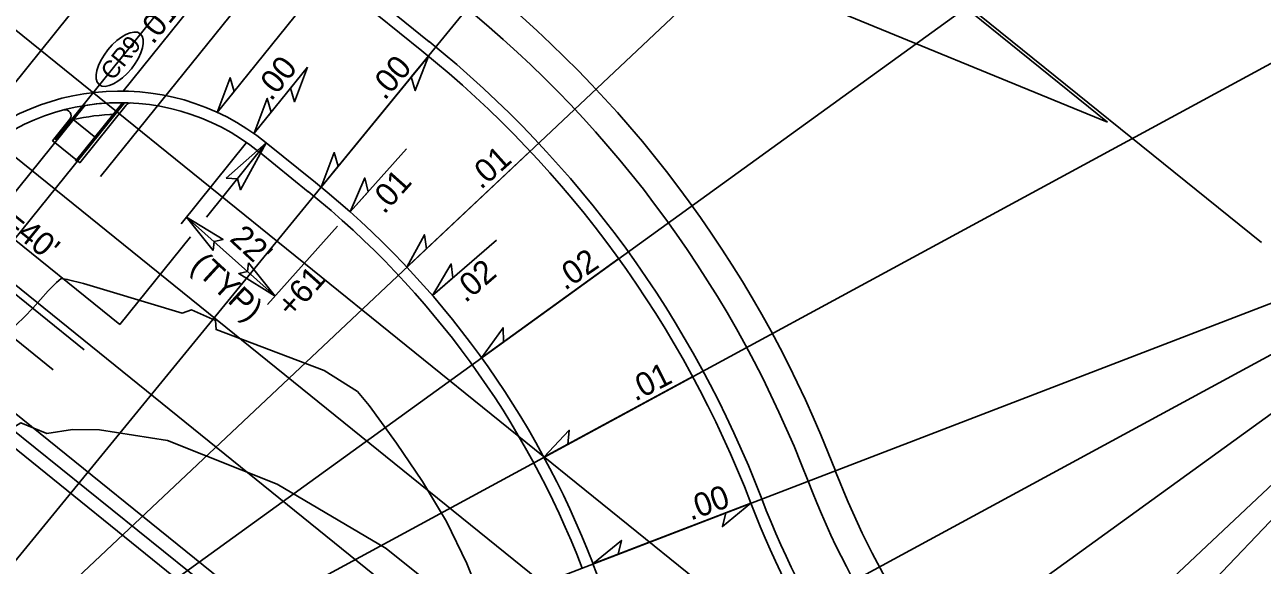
# Model space of a CAD drawing. Extents: x 1486489 to 1490134, y 497089 to 500876.
# Drawn here: x 1488844.3 to 1489056.4, y 499139.1 to 499231.7 of the extents above; entities that cross this region are included whole.
import ezdxf

# ---------------------------------------------------------------- set-up
doc = ezdxf.new("R2010")
doc.units = 0
for name, color, linetype in [('DEV PRELIMINARY STAMP CELL', 7, 'Continuous'), ('Gray Area Fill Shapes', 7, 'Continuous'), ('Old_Level_9', 7, 'Continuous'), ('Pattern 5', 7, 'Continuous'), ('Prop Horizontal Alignment Station Label', 7, 'Continuous'), ('Prop North Arrow NAD83 for Plan Sheets CELL', 7, 'Continuous'), ('Prop Rem of Exist Asph Pvmt', 7, 'Continuous'), ('Prop Text', 7, 'Continuous'), ('Prop WCC CELL', 7, 'Continuous'), ('Scratch_Level_0', 7, 'Continuous'), ('Scratch_Level_5', 7, 'Continuous'), ('Sheet Block Revision CELL', 7, 'Continuous'), ('Sheet Block Title CELL', 7, 'Continuous'), ('Sheet Border Standard 30in CELL', 7, 'Continuous'), ('Sheet Data Field CELL', 7, 'Continuous'), ('Sheet Plan CELL', 7, 'Continuous'), ('Sheet Sticker Exception Certification CELL', 7, 'Continuous')]:
    doc.layers.add(name, color=color, linetype=linetype)

msp = doc.modelspace()

# ---------------------------------------------------------------- linework, layer by layer
at = {"layer": 'DEV PRELIMINARY STAMP CELL'}
for points in [[(1488892.75, 499224.41), (1488890.54, 499218.48), (1488889.84, 499220.81)], [(1488883.65, 499213.12), (1488885.86, 499219.05), (1488886.55, 499216.72)], [(1488900.08, 499199.62), (1488902.59, 499205.43), (1488903.16, 499203.07)], [(1488914.19, 499185.29), (1488917.42, 499190.72), (1488917.69, 499188.31)]]:
    msp.add_lwpolyline(points, close=True, dxfattribs=at)
at = {"layer": 'Gray Area Fill Shapes'}
for p, q in [((1488861.18, 499220.32), (1488889.33, 499255.21)), ((1488883.65, 499213.12), (1488892.75, 499224.41)), ((1488871.09, 499197.56), (1488882.33, 499211.49)), ((1488900.08, 499199.62), (1488909.74, 499210.44)), ((1488872.05, 499198.74), (1488887.22, 499185.2)), ((1488885.93, 499183.76), (1488897.92, 499197.19)), ((1488914.19, 499185.29), (1488925.16, 499194.77))]:
    msp.add_line(p, q, dxfattribs=at)
for points in [[(1488876.6, 499193.02), (1488872.05, 499198.74), (1488878.3, 499194.88), (1488876.77, 499194.53)], [(1488882.67, 499190.92), (1488887.22, 499185.2), (1488880.97, 499189.07), (1488882.51, 499189.41)]]:
    msp.add_lwpolyline(points, close=True, dxfattribs=at)
at = {"layer": 'Old_Level_9'}
msp.add_lwpolyline([(1489125.56, 498933.79), (1489105.79, 498950), (1489083.46, 498967.96), (1489053.28, 498992.22), (1489018.86, 499019.95), (1488995.28, 499038.96), (1488972.75, 499057.15), (1488947.35, 499077.62), (1488919.48, 499100.08), (1488890.07, 499123.82), (1488841.68, 499162.79)], dxfattribs=at)
at = {"layer": 'Pattern 5'}
for p, q in [((1488854.57, 499217.84), (1488852.62, 499215.42)), ((1488859.76, 499216.31), (1488861.37, 499218.31))]:
    msp.add_line(p, q, dxfattribs=at)
for radius, start, end in [(38, 88.8385, 99.1393), (36, 91.3438, 102.8106)]:
    msp.add_arc((1488860.6, 499180.32), radius, start, end, dxfattribs=at)
at = {"layer": 'Prop Horizontal Alignment Station Label'}
for p, q in [((1488802.6, 499153.4), (1488854.57, 499217.84)), ((1488806.49, 499150.26), (1488861.37, 499218.31)), ((1488852.62, 499215.42), (1488856.51, 499212.28)), ((1488849.45, 499211.5), (1488853.35, 499208.36))]:
    msp.add_line(p, q, dxfattribs=at)
for centre, radius, start, end in [((1488796.55, 499083.6), 200, 21.0099, 51.1156), ((1488796.55, 499083.6), 195, 21.0099, 51.1156), ((1489113.94, 499205.5), 140, 201.0099, 226.343), ((1489113.94, 499205.5), 145, 201.0099, 226.343)]:
    msp.add_arc(centre, radius, start, end, dxfattribs=at)
at = {"layer": 'Prop North Arrow NAD83 for Plan Sheets CELL'}
for p, q in [((1488853.74, 499208.05), (1488861.68, 499217.9)), ((1488849.07, 499211.81), (1488852.03, 499215.49)), ((1488849.45, 499211.5), (1488849.07, 499211.81)), ((1488853.35, 499208.36), (1488853.74, 499208.05))]:
    msp.add_line(p, q, dxfattribs=at)
for centre, start, end in [((1488851.25, 499216.12), 321.1156, 104.6346), ((1488862.46, 499217.27), 87.1194, 141.1156)]:
    msp.add_arc(centre, 1, start, end, dxfattribs=at)
at = {"layer": 'Prop Rem of Exist Asph Pvmt'}
for points in [[(1488851.59, 499188.06), (1488851.59, 499188.06), (1488850.55, 499188.19), (1488849.75, 499187.55), (1488849.04, 499186.84), (1488848.34, 499186.12), (1488847.01, 499184.62), (1488845.67, 499183.13), (1488844.28, 499181.68), (1488842.85, 499180.27), (1488839.05, 499176.9), (1488839.05, 499176.9), (1488826.62, 499161.24), (1488825.46, 499159.61), (1488825.49, 499159.29)], [(1488901.34, 499168.89), (1488895.62, 499172.45), (1488877.11, 499179.47), (1488877.01, 499181.04), (1488872.89, 499182.88), (1488871.27, 499182.3), (1488858.96, 499186.01), (1488854.36, 499187.39), (1488851.59, 499188.06)], [(1488923.18, 499128.44), (1488923.08, 499131.98), (1488920.07, 499139.43), (1488916.58, 499146.6), (1488912.5, 499153.45), (1488908.04, 499160.04), (1488903.34, 499166.45), (1488901.34, 499168.89)], [(1488835.33, 499159.37), (1488837.47, 499159.52), (1488839.95, 499160.56), (1488840.75, 499161.43), (1488841.95, 499162.48), (1488843.63, 499163.5), (1488848.1, 499161.65), (1488852.51, 499162.38)], [(1488852.51, 499162.38), (1488857.14, 499162.31), (1488868.78, 499160.49), (1488887.58, 499153.02), (1488906.23, 499141.98), (1488923.18, 499128.44)]]:
    msp.add_lwpolyline(points, dxfattribs=at)
at = {"layer": 'Prop Text'}
for p, q in [((1489031.06, 499369.78), (1488777.53, 499060.39)), ((1488774.7, 499063.04), (1489066.03, 499337.13)), ((1488891.01, 499263.42), (1488849.49, 499211.94)), ((1488898.79, 499257.15), (1488857.27, 499205.66)), ((1488858.52, 498937.81), (1489134.65, 499227.2))]:
    msp.add_line(p, q, dxfattribs=at)
at = {"layer": 'Prop WCC CELL'}
msp.add_ellipse((1488860.57, 499225.77), major_axis=(3.52, 4.36), ratio=0.462467, dxfattribs=at)
at = {"layer": 'Scratch_Level_0'}
for p, q in [((1488992.27, 499245.35), (1489029.89, 499215.01)), ((1488972.46, 499238.55), (1489029.89, 499215.01)), ((1488852.98, 499208.3), (1488861.05, 499218.32)), ((1488885.71, 499211.46), (1488875.44, 499198.73)), ((1488829.46, 499205.43), (1488860.6, 499180.32)), ((1488872.72, 499195.35), (1488860.6, 499180.32))]:
    msp.add_line(p, q, dxfattribs=at)
msp.add_lwpolyline([(1488878.85, 499205.42), (1488885.71, 499211.46), (1488881.28, 499203.41), (1488880.75, 499205.31)], close=True, dxfattribs=at)
at = {"layer": 'Scratch_Level_5'}
for p, q in [((1488913.62, 499228.77), (1488901.28, 499238.73)), ((1488892.91, 499203.08), (1488884.46, 499209.9))]:
    msp.add_line(p, q, dxfattribs=at)
for centre, radius, start, end in [((1488796.55, 499083.6), 186.5, 21.0099, 51.1156), ((1488860.6, 499180.32), 38, 51.1156, 141.1156), ((1488796.55, 499083.6), 153.5, 21.0099, 51.1156), ((1489113.94, 499205.5), 153.5, 201.0099, 226.343)]:
    msp.add_arc(centre, radius, start, end, dxfattribs=at)
at = {"layer": 'Sheet Block Revision CELL'}
for p, q in [((1488854.5, 499176.01), (1488775.54, 499239.69)), ((1488849.19, 499172.57), (1488771.4, 499235.48))]:
    msp.add_line(p, q, dxfattribs=at)
at = {"layer": 'Sheet Block Title CELL'}
msp.add_line((1488829.46, 499205.43), (1488913.13, 499309.18), dxfattribs=at)
at = {"layer": 'Sheet Border Standard 30in CELL'}
for p, q in [((1488777.53, 499060.39), (1489031.06, 499369.78)), ((1489066.03, 499337.13), (1488774.7, 499063.04)), ((1488772.23, 499066.03), (1489096.5, 499300.23)), ((1489121.95, 499259.71), (1488770.16, 499069.32)), ((1489135.79, 499226.06), (1488844.47, 498951.95)), ((1488814, 498988.85), (1489138.26, 499223.06)), ((1489140.33, 499219.78), (1488788.55, 499029.37)), ((1488768.54, 499072.84), (1489141.95, 499216.25))]:
    msp.add_line(p, q, dxfattribs=at)
at = {"layer": 'Sheet Data Field CELL'}
for p, q in [((1488877.31, 499216.66), (1488896.52, 499240.49)), ((1488895.11, 499203.87), (1488913.49, 499226.3)), ((1488913.49, 499226.3), (1488895.11, 499203.87)), ((1488909.8, 499190.15), (1488930.93, 499210.02)), ((1488922.61, 499174.64), (1488946.12, 499191.62)), ((1488933.3, 499157.61), (1488958.81, 499171.42)), ((1488968.78, 499149.75), (1488941.71, 499139.35)), ((1488941.71, 499139.35), (1488968.78, 499149.75))]:
    msp.add_line(p, q, dxfattribs=at)
for points in [[(1488913.49, 499226.3), (1488911.23, 499220.4), (1488910.56, 499222.73)], [(1488877.31, 499216.66), (1488879.51, 499222.59), (1488880.21, 499220.26)], [(1488895.11, 499203.87), (1488897.36, 499209.78), (1488898.04, 499207.45)], [(1488909.8, 499190.15), (1488912.8, 499195.72), (1488913.17, 499193.32)], [(1488922.61, 499174.64), (1488926.3, 499179.78), (1488926.36, 499177.35)], [(1488933.3, 499157.61), (1488937.63, 499162.23), (1488937.37, 499159.81)], [(1488968.78, 499149.75), (1488963.9, 499145.73), (1488964.46, 499148.09)], [(1488941.71, 499139.35), (1488946.59, 499143.37), (1488946.03, 499141.01)]]:
    msp.add_lwpolyline(points, close=True, dxfattribs=at)
at = {"layer": 'Sheet Plan CELL'}
for p, q in [((1488744.94, 499445.5), (1489056.31, 499194.4)), ((1488989.91, 499112.07), (1488678.54, 499363.17)), ((1488667.87, 499349.94), (1488979.24, 499098.84)), ((1488968.56, 499085.6), (1488657.2, 499336.7)), ((1488646.42, 499323.34), (1488957.79, 499072.24)), ((1488954.87, 499068.62), (1488643.5, 499319.72))]:
    msp.add_line(p, q, dxfattribs=at)
at = {"layer": 'Sheet Sticker Exception Certification CELL'}
for p, q in [((1488912.37, 499227.21), (1488900.02, 499237.17)), ((1488894.16, 499204.64), (1488885.71, 499211.46))]:
    msp.add_line(p, q, dxfattribs=at)
for centre, radius, start, end in [((1488796.55, 499083.6), 184.5, 21.0099, 51.1156), ((1488860.6, 499180.32), 40, 51.1156, 141.1156), ((1488796.55, 499083.6), 155.5, 21.0099, 51.1156), ((1489113.94, 499205.5), 155.5, 201.0099, 226.343), ((1489113.94, 499205.5), 184.5, 201.0099, 209.4913)]:
    msp.add_arc(centre, radius, start, end, dxfattribs=at)

# ---------------------------------------------------------------- texts
at = {"layer": 'DEV PRELIMINARY STAMP CELL'}
for s, p in [("22'", (1488879.24, 499194.8)), ('(TYP)', (1488872.54, 499190.09))]:
    msp.add_text(s, height=4, rotation=317.4083, dxfattribs=at).set_placement(p)
at = {"layer": 'Gray Area Fill Shapes'}
for s, rotation, p in [('.01', 51.1156, (1488866.27, 499228.15)), ('.00', 51.1156, (1488886.54, 499218.44)), ('.01', 48.2542, (1488905.91, 499199.08)), ('.02', 40.8394, (1488919.84, 499183.93)), ('+61', 48.2542, (1488890.11, 499181.29))]:
    msp.add_text(s, height=4, rotation=rotation, dxfattribs=at).set_placement(p)
at = {"layer": 'Prop WCC CELL'}
msp.add_text('CR9', height=3, rotation=51.1156, dxfattribs=at).set_placement((1488859.39, 499221.96))
at = {"layer": 'Scratch_Level_0'}
msp.add_text("R=40'", height=4, rotation=321.1156, dxfattribs=at).set_placement((1488837.31, 499199.84))
at = {"layer": 'Sheet Data Field CELL'}
for s, rotation, p in [('.00', 49.2895, (1488906, 499218.58)), ('.01', 41.8747, (1488922.5, 499203.32)), ('.02', 34.46, (1488936.9, 499186.07)), ('.01', 27.0452, (1488948.95, 499167.1)), ('.00', 19.6321, (1488958.45, 499146.74))]:
    msp.add_text(s, height=4, rotation=rotation, dxfattribs=at).set_placement(p)

doc.saveas('drawing.dxf')
